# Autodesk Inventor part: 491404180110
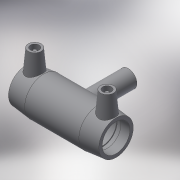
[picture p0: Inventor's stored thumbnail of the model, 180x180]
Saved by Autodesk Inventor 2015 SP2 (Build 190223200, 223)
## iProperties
Created: 2017-06
Part Number: 491404180110
Material: Generic
Description: PLASSON REDUCING TEE 180x110x180
Document SubType Name: Modeling
Designer: KIM
Mass: 57.3761 g
Surface Area: 241.06 cm^2
Volume: 57.3761 cm^3
Density: 1 g/cm^3
Appearance: Default
Author: KIM
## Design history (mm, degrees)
derived "491404.ipt"
feature "Solid1::491404.ipt"
tag "TaggingFeature1"
body "Solid1"
other parameters: "d0" = 422, "d2" = 245, "d3" = 106, "d4" = 84.4, "d5" = 220.5, "d6" = 171, "d8" = 168 deg, "d10" = 42.4, "d11" = 14.13333, "d13" = 422, "d14" = 17.6296, "d17" = 162, "d19" = 3.52592, "d20" = 168 deg, "d22" = 227.85, "d23" = 245, "d25" = 135 deg, "d26" = 295.4, "d29" = 116, "d30" = 15, "d31" = 168.8, "d34" = 5 deg, "d35" = 15, "d39" = 5 deg, "d41" = 4, "d42" = 14, "d43" = 0, "d45" = 4, "d46" = 6, "d47" = 0, "d48" = -219, "d51" = 0, "d52" = 88, "d54" = 0, "d55" = 220.5, "d56" = 245, "d57" = 147.7, "d58" = 135 deg, "d59" = 106, "d60" = 106, "d61" = 135 deg, "d62" = 219, "d72" = 192.01, "d73" = 96.005, "d74" = -219, "d75" = 115.5, "d77" = 0, "d78" = 88, "d80" = 0, "d82" = 96.5, "d83" = 0, "d84" = 3, "d85" = 0, "d86" = 35.33333, "d87" = 223.293, "d88" = 14.13333, "d89" = 3, "d90" = 0, "L_" = 422, "L_1" = 106, "D_" = 245, "A_" = 116, "d_2" = 12, "H_" = 219
